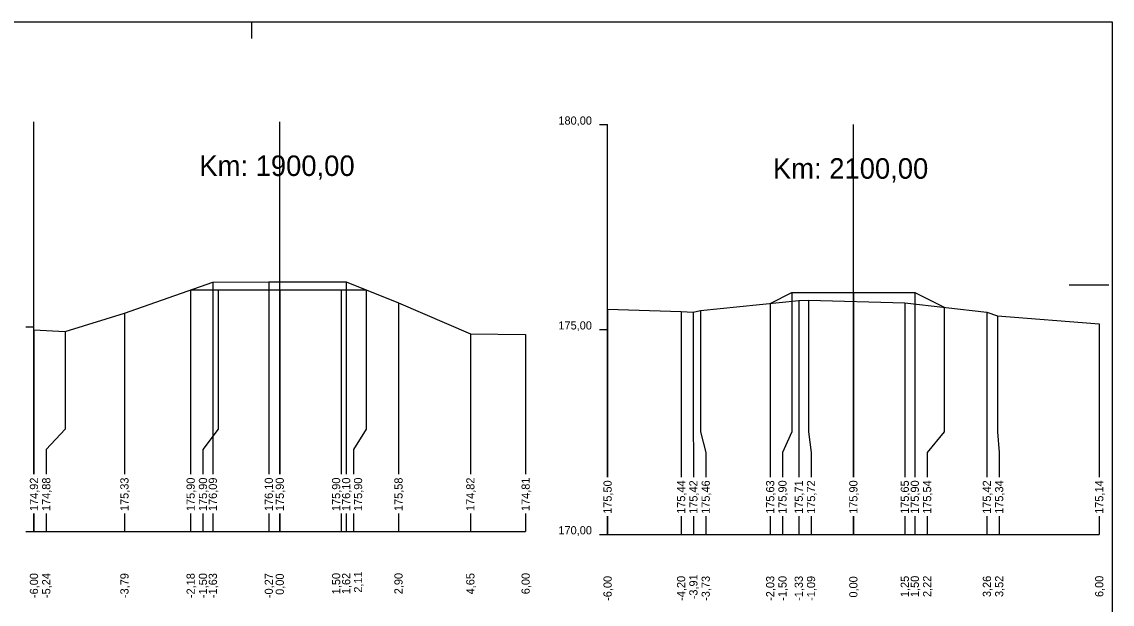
# Model space of a CAD drawing. Extents: x -614174 to -599765, y -1185887 to -1181080.
# Drawn here: x -612592.33 to -612565.71, y -1184200.94 to -1184186.72 of the extents above; entities that cross this region are included whole.
import ezdxf

# ---------------------------------------------------------------- set-up
doc = ezdxf.new("R2010")
doc.units = 0
for name, color, linetype in [('11', 7, 'Continuous'), ('16', 7, 'Continuous'), ('21', 7, 'Continuous'), ('28', 7, 'Continuous'), ('59', 7, 'Continuous'), ('8', 7, 'Continuous'), ('návrh', 7, 'Continuous')]:
    doc.layers.add(name, color=color, linetype=linetype)

msp = doc.modelspace()

# ---------------------------------------------------------------- linework, layer by layer
for points in [[(-612592.029, -1184194.242), (-612591.271, -1184194.282), (-612589.821, -1184193.832), (-612587.664, -1184193.078), (-612586.297, -1184193.07), (-612584.409, -1184193.07), (-612583.132, -1184193.586), (-612581.378, -1184194.342), (-612580.029, -1184194.353)], [(-612588.205, -1184193.267), (-612587.53, -1184193.267), (-612586.03, -1184193.267), (-612584.53, -1184193.267), (-612583.923, -1184193.267)], [(-612587.53, -1184193.267), (-612587.53, -1184193.267)], [(-612586.03, -1184193.267), (-612586.03, -1184193.267)], [(-612584.53, -1184193.267), (-612584.53, -1184193.267)], [(-612574.06, -1184193.6), (-612573.53, -1184193.335), (-612572.03, -1184193.335), (-612570.53, -1184193.335), (-612569.814, -1184193.692)], [(-612573.53, -1184193.335), (-612573.53, -1184193.335)], [(-612572.03, -1184193.335), (-612572.03, -1184193.335)], [(-612570.53, -1184193.335), (-612570.53, -1184193.335)], [(-612578.029, -1184193.738), (-612576.234, -1184193.792), (-612575.938, -1184193.815), (-612575.76, -1184193.773), (-612573.363, -1184193.529), (-612573.122, -1184193.518), (-612570.775, -1184193.583), (-612568.771, -1184193.812), (-612568.514, -1184193.898), (-612566.029, -1184194.096)], [(-612574.06, -1184193.6), (-612574.06, -1184193.6), (-612574.06, -1184193.6)]]:
    msp.add_lwpolyline(points)
at = {"layer": '11'}
for points in [[(-612587.664, -1184193.078), (-612587.664, -1184196.666), (-612587.664, -1184197.166), (-612587.664, -1184197.767)], [(-612586.297, -1184193.07), (-612586.297, -1184196.666), (-612586.297, -1184197.166), (-612586.297, -1184197.767)], [(-612584.409, -1184193.07), (-612584.409, -1184196.666), (-612584.409, -1184197.166), (-612584.409, -1184197.767)], [(-612588.205, -1184193.267), (-612588.205, -1184196.666), (-612588.205, -1184197.166), (-612588.205, -1184197.767)], [(-612587.53, -1184193.267), (-612587.53, -1184196.666), (-612587.905, -1184197.166), (-612587.905, -1184197.767)], [(-612586.03, -1184193.267), (-612586.03, -1184196.666), (-612586.03, -1184197.166), (-612586.03, -1184197.767)], [(-612584.53, -1184193.267), (-612584.53, -1184196.666), (-612584.53, -1184197.166), (-612584.53, -1184197.767)], [(-612583.923, -1184193.267), (-612583.923, -1184196.666), (-612584.23, -1184197.166), (-612584.23, -1184197.767)], [(-612573.53, -1184193.335), (-612573.53, -1184196.734), (-612573.76, -1184197.234), (-612573.76, -1184197.835)], [(-612572.03, -1184193.335), (-612572.03, -1184196.734), (-612572.03, -1184197.234), (-612572.03, -1184197.835)], [(-612570.53, -1184193.335), (-612570.53, -1184196.734), (-612570.53, -1184197.234), (-612570.53, -1184197.835)], [(-612583.132, -1184193.586), (-612583.132, -1184196.666), (-612583.132, -1184197.166), (-612583.132, -1184197.767)], [(-612574.06, -1184193.6), (-612574.06, -1184196.734), (-612574.06, -1184197.234), (-612574.06, -1184197.835)], [(-612573.363, -1184193.529), (-612573.363, -1184196.734), (-612573.363, -1184197.234), (-612573.363, -1184197.835)], [(-612573.122, -1184193.518), (-612573.122, -1184196.734), (-612573.063, -1184197.234), (-612573.063, -1184197.835)], [(-612570.775, -1184193.583), (-612570.775, -1184196.734), (-612570.775, -1184197.234), (-612570.775, -1184197.835)], [(-612589.821, -1184193.832), (-612589.821, -1184196.666), (-612589.821, -1184197.166), (-612589.821, -1184197.767)], [(-612578.029, -1184193.738), (-612578.029, -1184196.734), (-612578.029, -1184197.234), (-612578.029, -1184197.835)], [(-612576.234, -1184193.792), (-612576.234, -1184196.734), (-612576.234, -1184197.234), (-612576.234, -1184197.835)], [(-612575.938, -1184193.815), (-612575.938, -1184196.734), (-612575.934, -1184197.234), (-612575.934, -1184197.835)], [(-612575.76, -1184193.773), (-612575.76, -1184196.734), (-612575.634, -1184197.234), (-612575.634, -1184197.835)], [(-612569.814, -1184193.692), (-612569.814, -1184196.734), (-612570.23, -1184197.234), (-612570.23, -1184197.835)], [(-612568.771, -1184193.812), (-612568.771, -1184196.734), (-612568.771, -1184197.234), (-612568.771, -1184197.835)], [(-612568.514, -1184193.898), (-612568.514, -1184196.734), (-612568.471, -1184197.234), (-612568.471, -1184197.835)], [(-612566.029, -1184194.096), (-612566.029, -1184196.734), (-612566.029, -1184197.234), (-612566.029, -1184197.835)], [(-612592.029, -1184194.242), (-612592.029, -1184196.666), (-612592.029, -1184197.166), (-612592.029, -1184197.767)], [(-612591.271, -1184194.282), (-612591.271, -1184196.666), (-612591.729, -1184197.166), (-612591.729, -1184197.767)], [(-612581.378, -1184194.342), (-612581.378, -1184196.666), (-612581.378, -1184197.166), (-612581.378, -1184197.767)], [(-612580.029, -1184194.353), (-612580.029, -1184196.666), (-612580.029, -1184197.166), (-612580.029, -1184197.767)], [(-612592.029, -1184198.726), (-612592.029, -1184199.166)], [(-612591.729, -1184198.726), (-612591.729, -1184199.166)], [(-612589.821, -1184198.726), (-612589.821, -1184199.166)], [(-612588.205, -1184198.726), (-612588.205, -1184199.166)], [(-612587.905, -1184198.726), (-612587.905, -1184199.166)], [(-612587.664, -1184198.726), (-612587.664, -1184199.166)], [(-612586.297, -1184198.726), (-612586.297, -1184199.166)], [(-612586.03, -1184198.726), (-612586.03, -1184199.166)], [(-612584.53, -1184198.726), (-612584.53, -1184199.166)], [(-612584.409, -1184198.726), (-612584.409, -1184199.166)], [(-612584.23, -1184198.726), (-612584.23, -1184199.166)], [(-612583.132, -1184198.726), (-612583.132, -1184199.166)], [(-612581.378, -1184198.726), (-612581.378, -1184199.166)], [(-612580.029, -1184198.726), (-612580.029, -1184199.166)], [(-612578.029, -1184198.794), (-612578.029, -1184199.234)], [(-612576.234, -1184198.794), (-612576.234, -1184199.234)], [(-612575.934, -1184198.794), (-612575.934, -1184199.234)], [(-612575.634, -1184198.794), (-612575.634, -1184199.234)], [(-612574.06, -1184198.794), (-612574.06, -1184199.234)], [(-612573.76, -1184198.794), (-612573.76, -1184199.234)], [(-612573.363, -1184198.794), (-612573.363, -1184199.234)], [(-612573.063, -1184198.794), (-612573.063, -1184199.234)], [(-612572.03, -1184198.794), (-612572.03, -1184199.234)], [(-612570.775, -1184198.794), (-612570.775, -1184199.234)], [(-612570.53, -1184198.794), (-612570.53, -1184199.234)], [(-612570.23, -1184198.794), (-612570.23, -1184199.234)], [(-612568.771, -1184198.794), (-612568.771, -1184199.234)], [(-612568.471, -1184198.794), (-612568.471, -1184199.234)], [(-612566.029, -1184198.794), (-612566.029, -1184199.234)]]:
    msp.add_lwpolyline(points, dxfattribs=at)
at = {"layer": '16'}
for p, q in [((-612592.029, -1184199.166), (-612580.029, -1184199.166)), ((-612578.029, -1184199.234), (-612566.029, -1184199.234))]:
    msp.add_line(p, q, dxfattribs=at)
for points in [[(-612583.923, -1184193.267), (-612583.923, -1184193.267), (-612583.923, -1184193.267)], [(-612569.815, -1184193.692), (-612569.814, -1184193.692), (-612569.814, -1184193.692)]]:
    msp.add_lwpolyline(points, dxfattribs=at)
at = {"layer": '21'}
for p, q in [((-612578.229, -1184189.234), (-612578.029, -1184189.234)), ((-612592.229, -1184194.166), (-612592.029, -1184194.166)), ((-612578.229, -1184194.234), (-612578.029, -1184194.234)), ((-612592.229, -1184199.166), (-612592.029, -1184199.166)), ((-612578.229, -1184199.234), (-612578.029, -1184199.234))]:
    msp.add_line(p, q, dxfattribs=at)
at = {"layer": '28'}
for p, q in [((-612586.029, -1184197.767), (-612586.029, -1184189.166)), ((-612572.029, -1184197.835), (-612572.029, -1184189.234)), ((-612586.029, -1184199.166), (-612586.029, -1184198.726)), ((-612572.029, -1184199.234), (-612572.029, -1184198.794))]:
    msp.add_line(p, q, dxfattribs=at)
at = {"layer": '8'}
for p, q in [((-612592.029, -1184197.767), (-612592.029, -1184189.166)), ((-612578.029, -1184197.835), (-612578.029, -1184189.234)), ((-612592.029, -1184199.166), (-612592.029, -1184198.726)), ((-612578.029, -1184199.234), (-612578.029, -1184198.794))]:
    msp.add_line(p, q, dxfattribs=at)
at = {"layer": 'návrh'}
for p, q in [((-612691.713, -1184186.724), (-612565.713, -1184186.724)), ((-612586.713, -1184187.134), (-612586.713, -1184186.753)), ((-612565.713, -1184186.724), (-612565.713, -1184252.543)), ((-612566.765, -1184193.143), (-612565.793, -1184193.143))]:
    msp.add_line(p, q, dxfattribs=at)

# ---------------------------------------------------------------- texts
msp.add_text('+', height=0.001).set_placement((-612588.205, -1184193.267))
at = {"layer": '16'}
for s, p in [('174,92', (-612591.929, -1184198.666)), ('174,88', (-612591.629, -1184198.666)), ('175,33', (-612589.721, -1184198.666)), ('175,90', (-612588.105, -1184198.666)), ('175,90', (-612587.805, -1184198.666)), ('176,09', (-612587.564, -1184198.666)), ('176,10', (-612586.197, -1184198.666)), ('175,90', (-612585.93, -1184198.666)), ('175,90', (-612584.554, -1184198.666)), ('176,10', (-612584.309, -1184198.666)), ('175,90', (-612584.019, -1184198.666)), ('175,58', (-612583.032, -1184198.666)), ('174,82', (-612581.278, -1184198.666)), ('174,81', (-612579.929, -1184198.666)), ('175,50', (-612577.929, -1184198.734)), ('175,44', (-612576.134, -1184198.734)), ('175,42', (-612575.834, -1184198.734)), ('175,46', (-612575.534, -1184198.734)), ('175,63', (-612573.96, -1184198.734)), ('175,90', (-612573.66, -1184198.734)), ('175,71', (-612573.263, -1184198.734)), ('175,72', (-612572.963, -1184198.734)), ('175,90', (-612571.93, -1184198.734)), ('175,65', (-612570.675, -1184198.734)), ('175,90', (-612570.43, -1184198.734)), ('175,54', (-612570.13, -1184198.734)), ('175,42', (-612568.671, -1184198.734)), ('175,34', (-612568.371, -1184198.734)), ('175,14', (-612565.929, -1184198.734))]:
    msp.add_text(s, height=0.2, rotation=90, dxfattribs=at).set_placement(p)
at = {"layer": '21'}
for s, p in [('180,00', (-612579.229, -1184189.234)), ('175,00', (-612579.229, -1184194.234)), ('170,00', (-612579.229, -1184199.234))]:
    msp.add_text(s, height=0.2, dxfattribs=at).set_placement(p)
at = {"layer": '28'}
for s, p in [('Km: 1900,00', (-612587.993, -1184190.487)), ('Km: 2100,00', (-612573.993, -1184190.554))]:
    msp.add_text(s, height=0.5, dxfattribs=at).set_placement(p)
at = {"layer": '59'}
for s, p in [('-6,00', (-612591.929, -1184200.789)), ('-5,24', (-612591.629, -1184200.789)), ('-3,79', (-612589.721, -1184200.79)), ('-2,18', (-612588.105, -1184200.79)), ('-1,50', (-612587.805, -1184200.789)), ('-1,63', (-612587.564, -1184200.79)), ('-0,27', (-612586.197, -1184200.79)), ('0,00', (-612585.93, -1184200.71)), ('1,50', (-612584.554, -1184200.696)), ('1,62', (-612584.309, -1184200.695)), ('2,11', (-612584.019, -1184200.658)), ('2,90', (-612583.032, -1184200.696)), ('4,65', (-612581.278, -1184200.698)), ('6,00', (-612579.929, -1184200.696)), ('-6,00', (-612577.929, -1184200.857)), ('-4,20', (-612576.134, -1184200.857)), ('-3,91', (-612575.834, -1184200.819)), ('-3,73', (-612575.534, -1184200.858)), ('-2,03', (-612573.96, -1184200.858)), ('-1,50', (-612573.66, -1184200.857)), ('-1,33', (-612573.263, -1184200.858)), ('-1,09', (-612572.963, -1184200.858)), ('0,00', (-612571.93, -1184200.777)), ('1,25', (-612570.675, -1184200.766)), ('1,50', (-612570.43, -1184200.764)), ('2,22', (-612570.13, -1184200.763)), ('3,26', (-612568.671, -1184200.765)), ('3,52', (-612568.371, -1184200.763)), ('6,00', (-612565.929, -1184200.764))]:
    msp.add_text(s, height=0.2, rotation=90, dxfattribs=at).set_placement(p)

doc.saveas('drawing.dxf')
